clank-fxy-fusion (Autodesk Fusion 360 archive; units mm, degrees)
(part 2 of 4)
sketch "Top Down" plane through (0, 0, 0) normal (0, 0, 1) x axis (1, 0, 0)
  line L1 (13.85, -5.7) -> (56.15, -5.7)
  line L2 (13.85, 36.6) -> (13.85, -5.7)
  line L3 (56.15, 36.6) -> (13.85, 36.6)
  line L4 (56.15, -5.7) -> (56.15, 36.6)
  line L5 (50.5, -0.05) -> (19.5, -0.05)
  line L6 (50.5, 30.95) -> (50.5, -0.05)
  line L7 (19.5, 30.95) -> (50.5, 30.95)
  line L8 (19.5, -0.05) -> (19.5, 30.95)
  line L9 (13.85, 15.45) -> (19.5, 15.45)
  line L10 (35, 36.6) -> (35, 30.95)
  line L11 (35, 15.45) -> (19.5, 15.45)
  line L12 (35, 30.95) -> (35, 15.45)
  line L13 (43.4585, -13.55) -> (45.4793, -10.05)
  line L14 (45.4793, -17.05) -> (43.4585, -13.55)
  line L15 (49.5207, -17.05) -> (45.4793, -17.05)
  line L16 (51.5415, -13.55) -> (49.5207, -17.05)
  line L17 (49.5207, -10.05) -> (51.5415, -13.55)
  line L18 (45.4793, -10.05) -> (49.5207, -10.05)
  line L19 (18.4585, -13.55) -> (20.4793, -10.05)
  line L20 (20.4793, -17.05) -> (18.4585, -13.55)
  line L21 (24.5207, -17.05) -> (20.4793, -17.05)
  line L22 (26.5415, -13.55) -> (24.5207, -17.05)
  line L23 (24.5207, -10.05) -> (26.5415, -13.55)
  line L24 (20.4793, -10.05) -> (24.5207, -10.05)
  line L25 (47.5, -13.55) -> (22.5, -13.55)
  line L26 (100, 14.2247) -> (80, 14.2247)
  line L27 (100, 65.9747) -> (100, 14.2247)
  line L28 (80, 65.9747) -> (100, 65.9747)
  line L29 (80, 14.2247) -> (80, 65.9747)
  line L30 (117, 0) -> (0, 0)
  line L31 (117, -20) -> (117, 0)
  line L32 (0, -20) -> (117, -20)
  line L33 (0, 0) -> (0, -20)
  line L34 (16, 90.9747) -> (16, 40.9747)
  line L35 (113, 90.9747) -> (16, 90.9747)
  line L36 (113, 14.2247) -> (113, 90.9747)
  line L37 (67, 14.2247) -> (113, 14.2247)
  line L38 (117, -21.75) -> (47.5, -21.75)
  line L39 (117, -23.15) -> (117, -21.75)
  line L40 (47.5, -23.15) -> (117, -23.15)
  line L41 (47.5, -21.75) -> (47.5, -23.15)
  line L42 (117, -22) -> (47.5, -22)
  line L43 (30.6969, -13.3244) -> (29.909, 15.3099)
  line L44 (39.3031, -13.3244) -> (40.091, 15.3099)
  line L45 (103.5, 0.15) -> (116.5, 0.15)
  line L46 (103.5, -4.85) -> (103.5, 0.15)
  line L47 (116.5, -4.85) -> (103.5, -4.85)
  line L48 (116.5, 0.15) -> (116.5, -4.85)
  line L49 (67, 40.9747) -> (16, 40.9747)
  line L50 (67, 14.2247) -> (67, 40.9747)
  line L51 (0, 1) -> (117, 1)
  line L52 (0, 13) -> (0, 1)
  line L53 (117, 13) -> (0, 13)
  line L54 (117, 1) -> (117, 13)
  line L55 (63.9793, 3) -> (61.9585, 6.5)
  line L56 (61.9585, 6.5) -> (63.9793, 10)
  line L57 (63.9793, 10) -> (68.0207, 10)
  line L58 (68.0207, 3) -> (63.9793, 3)
  line L59 (68.0207, 10) -> (70.0415, 6.5)
  line L60 (70.0415, 6.5) -> (68.0207, 3)
  line L61 (63.9793, -29.85) -> (61.9585, -26.35)
  line L62 (61.9585, -26.35) -> (63.9793, -22.85)
  line L63 (63.9793, -22.85) -> (68.0207, -22.85)
  line L64 (68.0207, -29.85) -> (63.9793, -29.85)
  line L65 (68.0207, -22.85) -> (70.0415, -26.35)
  line L66 (70.0415, -26.35) -> (68.0207, -29.85)
  line L67 (66, -26.35) -> (66, 6.5)
  line L68 (13.5, -4.85) -> (0.5, -4.85)
  line L69 (13.5, 0.15) -> (13.5, -4.85)
  line L70 (0.5, 0.15) -> (13.5, 0.15)
  line L71 (0.5, -4.85) -> (0.5, 0.15)
  line L72 (0, 37.1) -> (0, 13)
  line L73 (56.65, 37.1) -> (0, 37.1)
  line L74 (56.65, -32.35) -> (56.65, 37.1)
  line L75 (0, -32.35) -> (56.65, -32.35)
  line L76 (0, 1) -> (0, -32.35)
  line L77 (103, -32.35) -> (56.65, -32.35)
  line L78 (103, 1) -> (103, -32.35)
  line L79 (103, 13.4747) -> (103, 1)
  line L80 (56.65, 13.4747) -> (103, 13.4747)
  line L81 (77.5815, -29.81) -> (72.5815, -29.81)
  line L82 (77.5815, -19) -> (77.5815, -29.81)
  line L83 (72.5815, -19) -> (77.5815, -19)
  line L84 (72.5815, -29.81) -> (72.5815, -19)
  line L85 (57.65, -16.46) -> (57.65, -32.35)
  line L86 (77.5815, -16.46) -> (57.65, -16.46)
  line L87 (77.5815, -15.46) -> (77.5815, -16.46)
  line L88 (56.65, -15.46) -> (77.5815, -15.46)
  line L89 (117, -5.7) -> (103, -5.7)
  line L90 (117, -32.35) -> (117, -5.7)
  line L91 (103, -32.35) -> (117, -32.35)
  line L92 (14, -8.85) -> (0, -8.85)
  line L93 (14, 13) -> (14, -8.85)
  line L94 (73, 1) -> (73, 13)
  line L95 (117, -17.5) -> (103, -17.5)
  line L96 (26.0622, 3.5) -> (22.0207, 3.5)
  line L97 (22.0207, 3.5) -> (20, 7)
  line L98 (20, 7) -> (22.0207, 10.5)
  line L99 (22.0207, 10.5) -> (26.0622, 10.5)
  line L100 (28.0829, 7) -> (26.0622, 3.5)
  line L101 (26.0622, 10.5) -> (28.0829, 7)
  line L102 (24.0415, 7) -> (0, 7)
  line L103 (21.3834, 13) -> (21.9245, 6.8148)
  line L104 (19.4009, 13) -> (19.9571, 6.6427)
  line L105 (26.6995, 13) -> (26.1584, 6.8148)
  line L106 (28.682, 13) -> (28.1259, 6.6427)
  line L107 (73, 13.4747) -> (73, 13)
  line L108 (77, -32.35) -> (77, 90.9747)
  line L109 (14, -32.35) -> (14, -8.85)
  line L110 (65.1915, 19.4747) -> (63.1707, 15.9747)
  line L111 (59.1293, 22.9747) -> (63.1707, 22.9747)
  line L112 (57.1085, 19.4747) -> (59.1293, 22.9747)
  line L113 (59.1293, 15.9747) -> (57.1085, 19.4747)
  line L114 (63.1707, 15.9747) -> (59.1293, 15.9747)
  line L115 (63.1707, 22.9747) -> (65.1915, 19.4747)
  line L116 (66.15, 25.4747) -> (66.15, 13.4747)
  line L117 (56.65, 25.4747) -> (66.15, 25.4747)
  line L118 (33.0442, -7.55) -> (32.5754, -14.2545)
  line L119 (35, -13.55) -> (35, 15.45)
  line L120 (36.9558, -7.55) -> (37.4246, -14.2545)
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  point P10 (19.5, 15.45)
  point P12 (35, 30.95)
  point P13 (35, 36.6)
  point P11 (13.85, 15.45)
  point P15 (35, 30.95)
  point P18 (47.5, -13.55)
  point P26 (47.5, -13.55)
  point P19 (22.5, -13.55)
  point P33 (22.5, -13.55)
  point P17 (22.5, -13.55)
  point P34 (22.5, -13.55)
  point P35 (47.5, -13.55)
  point P1 (0, 0)
  point P40 (0, 0)
  point P37 (100, 14.2247)
  point P16 (47.5, -13.55)
  point P54 (47.5, -22)
  point P55 (117, -22)
  point P41 (117, 0)
  point P14 (35, 15.45)
  point P56 (35, 15.45)
  point P61 (16, 65.9747)
  point P49 (67, 14.2247)
  point P67 (67, 14.2247)
  point P46 (113, 90.9747)
  point P47 (113, 90.9747)
  point P75 (66, 6.5)
  point P81 (66, 6.5)
  point P72 (66, 6.5)
  point P85 (66, -26.35)
  point P91 (66, -26.35)
  point P82 (66, -26.35)
  point P92 (66, 6.5)
  point P83 (66, -26.35)
  point P93 (66, -26.35)
  point P64 (103.5, -4.85)
  point P98 (7, -4.85)
  point P69 (0, 1)
  point P103 (0, 1)
  point P105 (103, 1)
  point P107 (56.65, 13.4747)
  point P112 (57.65, -32.35)
  point P116 (56.65, -15.46)
  point P110 (77.5815, -19)
  point P117 (103, -5.7)
  point P104 (103, -32.35)
  point P120 (103, -32.35)
  point P71 (117, 13)
  point P121 (0, -8.85)
  point P123 (14, 13)
  point P124 (73, 13)
  point P125 (73, 1)
  point P126 (103, -17.5)
  point P127 (117, -17.5)
  point P132 (24.0415, 7)
  point P137 (24.0415, 7)
  point P128 (24.0415, 7)
  point P136 (24.0415, 7)
  point P138 (0, 7)
  point P139 (24.0415, 7)
  point P140 (24.0415, 7)
  point P142 (21.3834, 13)
  point P144 (19.4009, 13)
  point P146 (26.6995, 13)
  point P148 (28.682, 13)
  point P150 (73, 13.4747)
  point P151 (110, 0.15)
  point P115 (77.5815, -15.46)
  point P149 (77.5815, -15.46)
  point P152 (77, 90.9747)
  point P153 (77, -32.35)
  point P154 (14, -32.35)
  point P158 (61.15, 19.4747)
  point P164 (61.15, 19.4747)
  point P162 (61.15, 19.4747)
  point P165 (66.15, 13.4747)
  point P167 (56.65, 25.4747)
  point P155 (61.15, 19.4747)
  point P168 (22.5, -13.55)
  point P172 (35, 15.45)
  point P173 (35, -13.55)
  point P174 (47.5, -13.55)
  point P189 (35, -18.55)
  point P191 (35, -18.55)
  point P185 (35, -18.55)
  point P192 (35, -18.55)
  point P182 (35, -18.55)
  point P196 (8.85, -16.2)
  point P202 (8.85, -16.2)
  point P200 (8.85, -16.2)
  point P203 (8.85, -16.2)
  point P207 (8.85, 27.1)
  point P213 (8.85, 27.1)
  point P211 (8.85, 27.1)
  point P214 (8.85, 27.1)
  point P215 (2.85, -8.85)
  point P216 (14, -23.55)
  point P193 (8.85, -16.2)
  point P219 (8.85, -16.2)
  point P221 (8.85, -16.2)
  point P204 (8.85, 27.1)
  point P222 (8.85, 27.1)
  point P223 (2.85, 13)
  point P224 (2.85, 37.1)
  point P226 (61.15, 19.4747)
  point P228 (61.15, 19.4747)
  point P230 (14.1839, -23.55)
  point P231 (14.1839, -23.55)
  point P232 (56.65, -6.3499)
  point P233 (14, 37.1)
  point P240 (61.15, 19.4747)
  point P239 (35, 15.45)
  point P241 (35, 15.45)
  point P242 (61.15, 19.4747)
  point P238 (35.2465, 14.0869)
  point P243 (35.2465, 14.0869)
  point P245 (56.65, -23.55)
  point P246 (0, -23.55)
  point P247 (22.5, -13.55)
  point P251 (22.5, -13.55)
  point P254 (90, 14.2247)
  point P255 (61.15, 19.4747)
  point P257 (61.15, 19.4747)
  point P244 (61.15, 19.4747)
  point P256 (61.15, 19.4747)
  point P3 (13.85, -5.7)
  point P4 (13.85, 36.6)
  point P6 (19.5, -0.05)
  point P9 (19.5, 30.95)
  point P22 (45.4793, -17.05)
  point P36 (80, 14.2247)
  point P43 (0, -20)
  point P44 (16, 40.9747)
  point P45 (16, 90.9747)
  point P50 (47.5, -21.75)
  point P53 (47.5, -23.15)
  point P63 (103.5, 0.15)
  point P62 (116.5, 0.15)
  point P38 (100, 65.9747)
  point P68 (117, 1)
  point P79 (63.9793, 3)
  point P73 (66, 6.5)
  point P89 (63.9793, -29.85)
  point P97 (0.5, 0.15)
  point P108 (72.5815, -29.81)
  point P109 (77.5815, -29.81)
  point P86 (70.0415, -26.35)
  point P122 (14, -8.85)
  point P133 (20, 7)
  point P100 (56.65, 37.1)
  point P94 (0.5, -4.85)
  point P119 (117, -32.35)
  point P101 (56.65, -32.35)
  point P157 (59.1293, 15.9747)
  point P180 (53.5, -7.55)
  point P225 (53.5, -6.55)
  point P106 (103, 13.4747)
  perpendicular L1 L2
  parallel L1 L3
  parallel L2 L4
  perpendicular L5 L6
  parallel L5 L7
  parallel L6 L8
  perpendicular L4 L5
  midpoint L8 P10
  perpendicular L8 L9
  midpoint L7 P12
  perpendicular L7 L10
  midpoint L3 P13
  midpoint L2 P11
  equal L2 L3
  equal L7 L8
  perpendicular L8 L11
  perpendicular L9 L12
  coincident P12 P15
  coincident P18 P26
  coincident P19 P33
  horizontal L24
  horizontal L18
  coincident P17 P34
  horizontal L25
  coincident P26 P35
  horizontal L26
  vertical L27
  horizontal L28
  vertical L29
  horizontal L30
  vertical L31
  horizontal L32
  vertical L33
  coincident P1 P40
  vertical L34
  horizontal L35
  perpendicular L36 L37
  coincident P37 L37
  horizontal L38
  vertical L39
  horizontal L40
  vertical L41
  coincident P16 L41
  coincident L41 P54
  coincident L39 P55
  perpendicular L39 L42
  coincident P41 L39
  coincident P14 P56
  midpoint L34 P61
  coincident L28 P61
  horizontal L45
  vertical L46
  horizontal L47
  vertical L48
  perpendicular L34 L49
  perpendicular L49 L50
  coincident P49 P67
  vertical L36
  coincident P46 P47
  horizontal L51
  vertical L52
  horizontal L53
  vertical L54
  coincident P75 P81
  horizontal L57
  coincident P72 P75
  coincident P85 P91
  horizontal L63
  coincident P82 P85
  coincident P75 P92
  perpendicular L63 L67
  coincident P83 P93
  coincident P41 L54
  horizontal L68
  vertical L69
  horizontal L70
  vertical L71
  equal L46 L71
  equal L47 L70
  coincident P64 L68
  midpoint L68 P98
  perpendicular L53 L72
  perpendicular L72 L73
  perpendicular L40 L74
  perpendicular L74 L75
  perpendicular L32 L76
  coincident P69 P103
  perpendicular L74 L77
  coincident L51 P105
  perpendicular L51 L78
  perpendicular L53 L79
  coincident L74 P107
  perpendicular L74 L80
  horizontal L81
  vertical L82
  horizontal L83
  vertical L84
  coincident L77 P112
  perpendicular L38 L85
  perpendicular L67 L86
  perpendicular L38 L87
  coincident L74 P116
  perpendicular L74 L88
  coincident P110 L87
  coincident L78 P117
  perpendicular L78 L89
  perpendicular L89 L90
  perpendicular L90 L91
  coincident P104 P120
  coincident P71 L90
  coincident L76 P121
  perpendicular L76 L92
  coincident L53 P123
  perpendicular L53 L93
  horizontal L1
  coincident L53 P124
  coincident L51 P125
  perpendicular L51 L94
  coincident L78 P126
  coincident L31 P127
  horizontal L95
  coincident P132 P137
  horizontal L99
  coincident P128 P136
  midpoint L52 P138
  perpendicular L93 L102
  coincident P137 P139
  coincident P128 P137
  coincident P137 P140
  coincident L53 P142
  coincident L53 P144
  parallel L103 L104
  coincident L53 P146
  coincident L53 P148
  parallel L105 L106
  coincident L80 P150
  perpendicular L80 L107
  midpoint L45 P151
  coincident P1 L76
  coincident P115 P149
  coincident L35 P152
  coincident L77 P153
  perpendicular L77 L108
  coincident L75 P154
  perpendicular L75 L109
  coincident P158 P164
  horizontal L111
  coincident P162 P164
  coincident L80 P165
  perpendicular L80 L116
  coincident L74 P167
  perpendicular L74 L117
  coincident P155 P164
  coincident P17 P168
  coincident P56 P172
  midpoint L25 P173
  perpendicular L25 L119
  coincident P18 P174
  coincident P189 P191
  coincident P185 P192
  coincident P182 P185
  coincident P196 P202
  coincident P200 P202
  coincident P196 P203
  coincident P207 P213
  coincident P211 P213
  coincident P207 P214
  coincident L92 P215
  coincident L109 P216
  coincident P193 P196
  coincident P193 P219
  coincident P202 P221
  coincident P204 P222
  coincident P204 P207
  coincident L53 P223
  coincident L73 P224
  coincident P155 P226
  coincident P155 P228
  coincident P230 P231
  coincident L74 P232
  coincident L73 P233
  coincident P158 P240
  coincident P56 P239
  coincident P56 P241
  coincident P155 P242
  coincident P238 P243
  coincident L74 P245
  coincident L76 P246
  coincident P182 P191
  coincident L119 P192
  coincident P17 P247
  coincident P33 P251
  midpoint L37 P254
  coincident P240 P255
  coincident P228 P257
  coincident P240 P244
  coincident P164 P256
  dimension "d583" distance P3 P4 = 42.3
  dimension "d584" distance P6 P9 = 31
  dimension "d588" diameter = 16.4
  dimension "d589" diameter = 4.25 (= "d628")
  dimension "d590" distance P22 L18 = 7 (= "hw_m4hex_d")
  dimension "d591" distance L21 L24 = 7 (= "d590")
  dimension "d592" distance P36 P37 = 20 (= "extrusion_w")
  dimension "d593" distance P40 P43 = 20 (= "extrusion_w")
  dimension "d596" distance P44 P45 = 50
  dimension "d597" distance L29 P49 = 13
  dimension "d598" distance P36 L36 = 33
  dimension "d599" distance P50 P53 = 1.4 (= "t_belt")
  dimension "d600" distance P50 L42 = 0.25 (= "belt_pdo_backside")
  dimension "d607" distance P34 P35 = 25
  dimension "d608" diameter = 10.1859 (= "( 16 * 2 / PI ) * 1 mm")
  dimension "d611" distance L25 P56 = 29
  dimension "d614" distance P63 P64 = 5 (= "t_bearings")
  dimension "d615" distance P62 P63 = 13 (= "od_bearings")
  dimension "d616" distance P38 L34 = 84
  dimension "d617" distance L49 P67 = 26.75
  dimension "d619" distance P68 P71 = 12
  dimension "d620" distance L45 L51 = 0.85 (= "t_m4_washer")
  dimension "d621" distance P41 L51 = 1
  dimension "d622" distance L48 L54 = 0.5
  dimension "d623" diameter = 13 (= "od_bearings")
  dimension "d624" diameter = 4.25 (= "d628")
  dimension "d625" distance P79 L57 = 7 (= "hw_m4hex_d")
  dimension "d626" distance L30 P73 = 6.5 (= "od_bearings / 2")
  dimension "d627" diameter = 13 (= "od_bearings")
  dimension "d628" diameter = 4.25
  dimension "d629" distance P89 L63 = 7 (= "hw_m4hex_d")
  dimension "d630" distance L32 P83 = 6.35 (= "od_bearings / 2 - preload")
  dimension "d631" distance L29 L67 = 14
  dimension "d635" distance L52 P97 = 0.5
  dimension "d636" distance P64 L78 = 0.5
  dimension "d637" distance P85 L77 = 6 (= "od_bearings / 2 - 0.5 mm")
  dimension "d647" distance L77 L81 = 2.54 (= "flex_t")
  dimension "d648" distance P108 P109 = 5 (= "flex_l")
  dimension "d649" distance P86 L84 = 2.54
  dimension "d651" distance L86 L88 = 1
  dimension "d652" distance L83 L86 = 2.54 (= "flex_t")
  dimension "d653" distance L32 L83 = 1
  dimension "d662" distance P64 L89 = 0.85 (= "t_m4_washer")
  dimension "d663" distance L69 P122 = 0.5
  dimension "d669" distance P4 L73 = 0.5
  dimension "d946" distance P73 L94 = 7 (= "od_bearings / 2 + 0.5 mm")
  dimension "d951" distance P71 L95 = 30.5
  dimension "d958" distance L96 L99 = 7 (= "d590")
  dimension "d959" distance L93 P133 = 6
  dimension "d960" diameter = 4.25 (= "d628")
  dimension "d961" diameter = 8.2
  dimension "d962" angle L8 L103 = 5
  dimension "d963" angle L8 L105 = 5
  dimension "d981" distance L4 P100 = 0.5
  dimension "d982" distance L27 P151 = 10
  dimension "d983" distance P94 L92 = 4
  dimension "d990" distance L76 P119 = 117
  dimension "d1027" distance P1 L12 = 35
  dimension "d1028" distance L12 L29 = 45
  dimension "d1029" distance P101 L85 = 1
  dimension "d1031" distance L29 P152 = 3
  dimension "d1033" diameter = 4.25 (= "d628")
  dimension "d1034" distance P157 L111 = 7 (= "hw_m4hex_d")
  dimension "d1035" distance L4 P158 = 5
  dimension "d1036" distance P162 L116 = 5
  dimension "d1037" distance L80 P162 = 6
  dimension "d1038" distance P158 L117 = 6 (= "d1037")
  dimension "d1039" distance = 1.9 (= "t_belt + 0.5 mm")
  dimension "d1042" angle L118 L119 = 4
  dimension "d1043" distance = 1.9 (= "t_belt + 0.5 mm")
  dimension "d1044" angle L119 L120 = 4
  dimension "d1045" distance = 10
  dimension "d1046" distance = 6 (= "od_bearings / 2 - 0.5 mm")
  dimension "d1047" distance = 6
  dimension "d1048" distance = 6
  dimension "d1049" diameter = 4.25 (= "d628")
  dimension "d1050" distance = 7 (= "hw_m4hex_d")
  dimension "d1051" diameter = 4.25 (= "d628")
  dimension "d1052" distance = 7 (= "hw_m4hex_d")
  dimension "d1053" diameter = 4.25 (= "d628")
  dimension "d1054" distance = 7 (= "hw_m4hex_d")
  dimension "d1055" distance = 11
  dimension "d1056" distance L73 P211 = 10
  dimension "d1057" distance P180 P225 = 1
  dimension "d1058" angle = 3
  dimension "d1059" angle = 3 (= "d1058")
  dimension "d1072" distance = 5
  dimension "d1075" radius = 8.5 (= "( 17 / 2 ) * 1 mm")
  dimension "d1076" angle = 3
  dimension "d1430" distance = 77.15
  dimension "d1680" distance L37 P106 = 0.75
  dimension "d1681" distance L32 L42 = 2
  dimension "d1682" distance L25 P191 = 5
  dimension "d1693" distance = 0.5
  dimension "d1697" distance L32 L73 = 57.1
  dimension "d1699" distance = 1.5
  dimension "d1760" distance L53 P165 = 0.4747
  dimension "d523" OffsetX = 0
  dimension "d524" OffsetY = 0
  dimension "d525" OffsetZ = 0
  dimension "d526" AngleZ = 0
  dimension "d567" OffsetX = 0
  dimension "d568" OffsetY = 0
  dimension "d569" OffsetZ = 0
  dimension "d570" AngleZ = 0
extrude "Extrude42" new body sketch "Top Down" along normal blind 9.5 (= "t_sheet_MAIN")
extrude "Extrude44" cut sketch "Top Down" to an object from offset 2
fillet "Fillet17" radius 0.5
fillet "Fillet18" radius 1.5
extrude "Extrude59" new body sketch "Top Down" profile of L51 L52 L53 L54 L79 L93 along normal blind 13.25 (= "od_bearings - 0.5 mm + 0.75 mm")
extrude "Extrude60" new body sketch "Top Down" against normal blind 34.25 (magnitude of "-extrusion_h - 0.75 mm - od_bearings - 0.5 mm")
combine "Combine13"
sketch "Side Plate" plane through (0, 1, 0) normal (0, -1, 0) x axis (1, 0, 0)
  line L1 (14, 0) -> (103, 0)
  line L2 (14, 13.25) -> (14, 0)
  line L3 (0, 13.25) -> (14, 13.25)
  line L4 (0, -34.25) -> (0, 13.25)
  line L5 (117, -34.25) -> (0, -34.25)
  line L6 (117, 13.25) -> (117, -34.25)
  line L7 (103, 13.25) -> (117, 13.25)
  line L8 (103, 0) -> (103, 13.25)
  line L9 (7, 5.75) -> (7, 13.25)
  line L10 (110, 5.75) -> (7, 5.75)
  line L11 (110, -27.1) -> (110, 5.75)
  line L12 (7, -27.1) -> (110, -27.1)
  line L13 (7, 5.75) -> (7, -27.1)
  line L14 (110, 5.75) -> (110, 13.25)
  line L15 (58.5, -34.25) -> (58.5, 0)
  line L16 (7, 9.7915) -> (10.5, 7.7707)
  line L17 (3.5, 7.7707) -> (7, 9.7915)
  line L18 (3.5, 3.7293) -> (3.5, 7.7707)
  line L19 (7, 1.7085) -> (3.5, 3.7293)
  line L20 (10.5, 3.7293) -> (7, 1.7085)
  line L21 (10.5, 7.7707) -> (10.5, 3.7293)
  line L22 (7, -23.0585) -> (10.5, -25.0793)
  line L23 (3.5, -25.0793) -> (7, -23.0585)
  line L24 (3.5, -29.1207) -> (3.5, -25.0793)
  line L25 (7, -31.1415) -> (3.5, -29.1207)
  line L26 (10.5, -29.1207) -> (7, -31.1415)
  line L27 (10.5, -25.0793) -> (10.5, -29.1207)
  line L28 (106.5, 3.7293) -> (110, 1.7085)
  line L29 (106.5, 7.7707) -> (106.5, 3.7293)
  line L30 (110, 9.7915) -> (106.5, 7.7707)
  line L31 (113.5, 7.7707) -> (110, 9.7915)
  line L32 (113.5, 3.7293) -> (113.5, 7.7707)
  line L33 (110, 1.7085) -> (113.5, 3.7293)
  line L34 (18.04, -31.71) -> (13.04, -31.71)
  line L35 (18.04, -24.14) -> (18.04, -31.71)
  line L36 (13.04, -24.14) -> (18.04, -24.14)
  line L37 (13.04, -31.71) -> (13.04, -24.14)
  line L38 (18.04, -21.6) -> (0, -21.6)
  line L39 (18.04, -20.6) -> (18.04, -21.6)
  line L40 (0, -20.6) -> (18.04, -20.6)
  line L41 (103.96, -31.71) -> (103.96, -24.14)
  line L42 (103.96, -24.14) -> (98.96, -24.14)
  line L43 (98.96, -24.14) -> (98.96, -31.71)
  line L44 (98.96, -31.71) -> (103.96, -31.71)
  line L45 (98.96, -20.6) -> (98.96, -21.6)
  line L46 (98.96, -21.6) -> (117, -21.6)
  line L47 (117, -20.6) -> (98.96, -20.6)
  line L48 (110, -23.0585) -> (106.5, -25.0793)
  line L49 (113.5, -25.0793) -> (110, -23.0585)
  line L50 (113.5, -29.1207) -> (113.5, -25.0793)
  line L51 (110, -31.1415) -> (113.5, -29.1207)
  line L52 (106.5, -29.1207) -> (110, -31.1415)
  line L53 (106.5, -25.0793) -> (106.5, -29.1207)
  line L54 (117, 0) -> (103, 0)
  line L55 (80, -20.75) -> (100, -20.75)
  line L56 (80, 39.25) -> (80, -20.75)
  line L57 (100, 39.25) -> (80, 39.25)
  line L58 (100, -20.75) -> (100, 39.25)
  line L59 (90, -20.75) -> (90, 39.25)
  line L60 (76.75, 13.75) -> (78.15, 13.75)
  line L61 (76.75, 24.75) -> (76.75, 13.75)
  line L62 (78.15, 24.75) -> (76.75, 24.75)
  line L63 (78.15, 13.75) -> (78.15, 24.75)
  line L64 (77, 13.75) -> (77, 24.75)
  line L65 (73, 0) -> (103, 0)
  line L66 (73, 9.5) -> (73, 0)
  line L67 (103, 9.5) -> (73, 9.5)
  line L68 (103, 0) -> (103, 9.5)
  line L69 (108.9, 49.75) -> (77, 49.75)
  line L70 (108.9, 9.5) -> (108.9, 49.75)
  line L71 (103, 9.5) -> (108.9, 9.5)
  line L72 (67.9, 12.75) -> (76.9, 12.75)
  line L73 (67.9, 49.75) -> (67.9, 12.75)
  line L74 (76.9, 49.75) -> (67.9, 49.75)
  line L75 (76.9, 12.75) -> (76.9, 49.75)
  line L76 (102.8, 13.45) -> (102.8, 9.5)
  line L77 (108.9, 13.45) -> (102.8, 13.45)
  line L78 (77, 49.75) -> (77, 24.75)
  line L79 (77, 9.5) -> (77, 13.75)
  line L80 (75.75, 24.75) -> (76.75, 24.75)
  line L81 (75.75, 13.75) -> (75.75, 24.75)
  line L82 (76.75, 13.75) -> (75.75, 13.75)
  line L83 (77, 49.75) -> (76.9, 49.75)
  line L84 (57.5, 9.5) -> (73, 9.5)
  line L85 (57.5, 49.75) -> (57.5, 9.5)
  line L86 (67.9, 49.75) -> (57.5, 49.75)
  line L87 (57.5, 12.25) -> (77, 12.25)
  line L88 (0, 0) -> (14, 0)
  line L89 (18.04, -20.6) -> (18.04, 0)
  line L90 (2.85, -20.6) -> (2.85, 0)
  line L91 (39.35, -13.2707) -> (39.35, -9.2293)
  line L92 (46.35, -13.2707) -> (42.85, -15.2915)
  line L93 (46.35, -9.2293) -> (46.35, -13.2707)
  line L94 (42.85, -7.2085) -> (46.35, -9.2293)
  line L95 (42.85, -15.2915) -> (39.35, -13.2707)
  line L96 (39.35, -9.2293) -> (42.85, -7.2085)
  line L97 (39.35, -28.2707) -> (39.35, -24.2293)
  line L98 (42.85, -30.2915) -> (39.35, -28.2707)
  line L99 (46.35, -28.2707) -> (42.85, -30.2915)
  line L100 (42.85, -22.2085) -> (46.35, -24.2293)
  line L101 (46.35, -24.2293) -> (46.35, -28.2707)
  line L102 (39.35, -24.2293) -> (42.85, -22.2085)
  line L103 (42.85, -11.25) -> (42.85, -26.25)
  circle C1 centre (7, 5.75) radius 2.125
  circle C2 centre (7, 5.75) radius 6.5
  circle C3 centre (7, -27.1) radius 2.125
  circle C4 centre (7, -27.1) radius 6.5
  circle C5 centre (110, 5.75) radius 2.125
  circle C6 centre (110, -27.1) radius 2.125
  circle C7 centre (90, 29.25) radius 2.75
  circle C8 centre (90, 9.25) radius 2.75
  circle C9 centre (90, -10.75) radius 2.75
  circle C10 centre (90, 9.25) radius 5.25
  circle C11 centre (90, 29.25) radius 5.25
  circle C12 centre (90, -10.75) radius 5.25
  circle C13 centre (42.85, -11.25) radius 2.125
  circle C14 centre (42.85, -26.25) radius 2.125
  point P12 (7, 13.25)
  point P11 (7, 5.75)
  point P13 (7, 5.75)
  point P10 (7, 5.75)
  point P17 (7, 5.75)
  point P15 (7, -27.1)
  point P20 (7, -27.1)
  point P21 (110, 13.25)
  point P18 (110, 5.75)
  point P22 (110, 5.75)
  point P23 (58.5, 0)
  point P24 (58.5, -34.25)
  point P31 (7, 5.75)
  point P38 (7, -27.1)
  point P25 (10.5, 7.7707)
  point P42 (106.5, 7.7707)
  point P26 (7, 9.7915)
  point P43 (110, 9.7915)
  point P27 (3.5, 7.7707)
  point P44 (113.5, 7.7707)
  point P28 (3.5, 3.7293)
  point P45 (113.5, 3.7293)
  point P29 (7, 1.7085)
  point P40 (110, 1.7085)
  point P30 (10.5, 3.7293)
  point P41 (106.5, 3.7293)
  point P50 (0, -21.6)
  point P53 (0, -20.6)
  point P51 (18.04, -21.6)
  point P32 (10.5, -25.0793)
  point P62 (106.5, -25.0793)
  point P33 (7, -23.0585)
  point P63 (110, -23.0585)
  point P34 (3.5, -25.0793)
  point P64 (113.5, -25.0793)
  point P35 (3.5, -29.1207)
  point P65 (113.5, -29.1207)
  point P36 (7, -31.1415)
  point P66 (110, -31.1415)
  point P37 (10.5, -29.1207)
  point P67 (106.5, -29.1207)
  point P46 (13.04, -31.71)
  point P55 (103.96, -31.71)
  point P47 (18.04, -31.71)
  point P57 (98.96, -31.71)
  point P48 (18.04, -24.14)
  point P56 (98.96, -24.14)
  point P49 (13.04, -24.14)
  point P54 (103.96, -24.14)
  point P60 (117, -21.6)
  point P58 (98.96, -21.6)
  point P52 (18.04, -20.6)
  point P59 (98.96, -20.6)
  point P61 (117, -20.6)
  point P2 (103, 0)
  point P69 (103, 0)
  point P70 (117, 0)
  point P71 (100, 0)
  point P72 (80, 0)
  point P77 (90, 39.25)
  point P78 (90, -20.75)
  point P79 (90, 29.25)
  point P80 (90, 9.25)
  point P81 (90, -10.75)
  point P88 (77, 24.75)
  point P89 (77, 13.75)
  point P90 (78.15, 19.25)
  point P94 (103, 9.5)
  point P98 (103, 9.5)
  point P95 (77, 49.75)
  point P104 (102.8, 9.5)
  point P106 (108.9, 13.45)
  point P108 (77, 9.5)
  point P107 (77, 49.75)
  point P85 (76.75, 13.75)
  point P111 (76.75, 13.75)
  point P93 (73, 9.5)
  point P112 (73, 9.5)
  point P101 (67.9, 49.75)
  point P115 (67.9, 49.75)
  point P116 (77, 12.25)
  point P117 (57.5, 12.25)
  point P3 (14, 0)
  point P119 (14, 0)
  point P14 (0, 0)
  point P120 (0, 0)
  point P121 (18.04, 0)
  point P122 (18.04, -20.6)
  point P123 (2.85, 0)
  point P124 (2.85, -20.6)
  point P125 (42.85, -11.25)
  point P127 (42.85, -11.25)
  point P134 (42.85, -11.25)
  point P126 (42.85, -11.25)
  point P138 (42.85, -26.25)
  point P143 (42.85, -26.25)
  point P139 (42.85, -26.25)
  point P136 (42.85, -26.25)
  point P145 (2.85, 0)
  point P146 (42.85, -26.25)
  point P147 (42.85, -11.25)
  point P16 (7, -27.1)
  point P73 (100, -20.75)
  point P76 (100, 39.25)
  point P86 (76.75, 24.75)
  point P87 (78.15, 24.75)
  point P84 (78.15, 13.75)
  point P75 (80, 39.25)
  point P102 (76.9, 49.75)
  point P96 (108.9, 49.75)
  point P9 (103, 13.25)
  point P109 (75.75, 24.75)
  point P100 (67.9, 12.75)
  point P118 (53.5, 0)
  point P129 (39.35, -9.2293)
  point P141 (39.35, -24.2293)
  concentric C1 C2
  midpoint L3 P12
  perpendicular L3 L9
  coincident P11 P13
  concentric C3 C4
  equal C2 C4
  equal C1 C3
  horizontal L10
  vertical L11
  horizontal L12
  vertical L13
  coincident P10 P17
  coincident P15 P20
  midpoint L7 P21
  perpendicular L7 L14
  coincident P18 P22
  midpoint L1 P23
  perpendicular L5 L15
  coincident L5 P24
  coincident P11 P31
  coincident P15 P38
  vertical L27
  vertical L21
  symmetric C1 L15 C5
  symmetric L15 P25 P42
  symmetric L15 P26 P43
  symmetric L15 P27 P44
  symmetric L15 P28 P45
  symmetric L15 P29 P40
  symmetric L15 P30 P41
  horizontal L34
  vertical L35
  horizontal L36
  vertical L37
  coincident L4 P50
  perpendicular L4 L38
  perpendicular L38 L39
  coincident L4 P53
  perpendicular L4 L40
  coincident L35 P51
  symmetric C3 L15 C6
  symmetric L15 P32 P62
  symmetric L15 P33 P63
  symmetric L15 P34 P64
  symmetric L15 P35 P65
  symmetric L15 P36 P66
  symmetric L15 P37 P67
  symmetric L15 P46 P55
  symmetric L15 P47 P57
  symmetric L15 P48 P56
  symmetric L15 P49 P54
  symmetric L15 P50 P60
  symmetric L15 P51 P58
  symmetric L15 P52 P59
  symmetric L15 P53 P61
  coincident P2 P69
  coincident L6 P70
  perpendicular L6 L54
  horizontal L55
  vertical L56
  horizontal L57
  vertical L58
  coincident P71 L58
  coincident P72 L56
  midpoint L57 P77
  midpoint L55 P78
  coincident L59 P79
  midpoint L59 P80
  coincident L59 P81
  equal C8 C9
  equal C7 C8
  concentric C8 C10
  concentric C7 C11
  equal C10 C11
  horizontal L60
  vertical L61
  horizontal L62
  vertical L63
  coincident L62 P88
  coincident L60 P89
  perpendicular L60 L64
  midpoint L63 P90
  perpendicular L61 L69
  perpendicular L7 L70
  perpendicular L70 L71
  coincident P94 P98
  horizontal L72
  vertical L73
  horizontal L74
  vertical L75
  coincident P95 L74
  concentric C9 C12
  equal C11 C12
  coincident L67 P104
  perpendicular L67 L76
  coincident L70 P106
  perpendicular L70 L77
  perpendicular L62 L78
  coincident L67 P108
  perpendicular L67 L79
  coincident P95 P107
  perpendicular L61 L80
  perpendicular L80 L81
  perpendicular L81 L82
  coincident P85 P111
  coincident P93 P112
  perpendicular L66 L84
  perpendicular L67 L85
  perpendicular L85 L86
  coincident P101 P115
  coincident L79 P116
  coincident L85 P117
  perpendicular L85 L87
  coincident P3 P119
  coincident P14 P120
  coincident L1 P121
  perpendicular L1 L89
  coincident P52 P122
  coincident L88 P123
  coincident L40 P124
  perpendicular L40 L90
  coincident P125 P127
  coincident P125 P134
  vertical L93
  coincident P125 P126
  coincident P138 P143
  coincident P139 P143
  vertical L101
  coincident P136 P143
  coincident L90 P145
  coincident P143 P146
  vertical L103
  coincident P126 P147
  dimension "d928" diameter C2 = 13 (= "od_bearings")
  dimension "d929" distance P10 P14 = 5.75 (= "od_bearings / 2 - 0.75 mm")
  dimension "d930" diameter C1 = 4.25
  dimension "d931" distance P10 P16 = 32.85 (= "extrusion_h + od_bearings - preload")
  dimension "d932" distance P34 L27 = 7 (= "hw_m4hex_d")
  dimension "d933" distance P28 L21 = 7 (= "hw_m4hex_d")
  dimension "d934" distance P51 P52 = 1
  dimension "d935" distance P48 P49 = 5 (= "flex_l")
  dimension "d936" distance L36 P51 = 2.54 (= "flex_t")
  dimension "d937" distance L5 L34 = 2.54 (= "flex_t")
  dimension "d938" distance P32 L37 = 2.54
  dimension "d939" distance P16 L38 = 5.5 (= "od_bearings / 2 - 1 mm")
  dimension "d984" distance P73 P76 = 60
  dimension "d986" distance L10 L55 = 26.5 (= "extrusion_h + od_bearings / 2")
  dimension "d987" diameter C7 = 5.5
  dimension "d988" distance L57 P79 = 10
  dimension "d989" distance L55 P81 = 10
  dimension "d997" diameter C10 = 10.5
  dimension "d1084" distance P86 L64 = 0.25 (= "belt_pdo_backside")
  dimension "d1085" distance P86 P87 = 1.4 (= "t_belt")
  dimension "d1086" distance L56 L64 = 3
  dimension "d1087" distance L57 P90 = 20
  dimension "d1088" distance P84 P87 = 11
  dimension "d1089" distance P75 L69 = 10.5
  dimension "d1091" distance P101 P102 = 9
  dimension "d1092" distance P96 L73 = 41
  dimension "d1093" distance P85 L72 = 1
  dimension "d1100" distance L7 L77 = 0.2
  dimension "d1101" distance P9 L76 = 0.2
  dimension "d1149" distance P95 L75 = 0.1
  dimension "d1150" distance P86 P109 = 1
  dimension "d1151" distance P100 L87 = 0.5
  dimension "d1155" distance L85 P118 = 4
  dimension "d1399" distance P129 L93 = 7 (= "hw_m4hex_d")
  dimension "d1401" distance L90 P126 = 40
  dimension "d1403" diameter C13 = 4.25 (= "hw_m4_thru")
  dimension "d1422" distance P141 L101 = 7 (= "hw_m4hex_d")
  dimension "d1423" diameter C14 = 4.25 (= "hw_m4_thru")
  dimension "d1426" distance L5 P136 = 8
  dimension "d1439" distance P125 P138 = 15
extrude "Extrude61" cut sketch "Side Plate" profile of L4 L6 C1 C3 C5 L34 L35 L36 L37 L38 L39 L40 L41 L42 L43 L44 L45 L46 L47 C6 L55 L58 to an object
extrude "Extrude62" cut sketch "Side Plate" profile of C1 C3 L16 L17 L18 L19 L20 L21 L22 L23 L24 L25 L26 L27 C5 L28 L29 L30 L31 L32 L33 L48 L49 L50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 to an object from offset -2.5
extrude "Extrude136" add of existing geometry blind 2
fillet "Fillet25" radius 0.5
extrude "Extrude63" cut sketch "Top Down" against normal blind 9.85 (magnitude of "-t_bearings - t_m4_washer - 4 mm")
fillet "Fillet30" radius 3
extrude "Extrude65" sketch "Side Plate" profile of L6 L7 L8 C5 L28 L29 L30 L31 L32 L33 L54 to an object
offset_faces "OffsetFaces8" distance -0.125
extrude "Extrude66" cut sketch "Top Down" blind -15 from offset -5.85 (= "-t_bearings - t_m4_washer")
extrude "Extrude67" sketch "Top Down" blind 2
extrude "Extrude68" cut sketch "Top Down" to an object
fillet "Fillet29" radius 2
extrude "Extrude69" cut sketch "Top Down" to an object
extrude "Extrude70" cut sketch "Top Down" to an object from offset 2
offset_faces "OffsetFaces5" distance -0.2
offset_faces "OffsetFaces6" distance -0.2
extrude "Extrude82" sketch "Top Down" blind 6 (= "t_motor_plates") from offset 15.2 (= "13.5 mm + t_m4_washer * 2")
extrude "Extrude83" sketch "Top Down" to an object offset -0.05
combine "Combine15"
sketch "Motor Plate" plane through (0, 0, 30.7) normal (0, 0, 1) x axis (-1, 0, 0)
  line L1 (-56.65, -13.4747) -> (-56.65, 6.3499)
  line L2 (-66.15, -13.4747) -> (-56.65, -13.4747)
  line L3 (-66.15, -25.4747) -> (-66.15, -13.4747)
  line L4 (-56.65, -25.4747) -> (-66.15, -25.4747)
  line L5 (-61.15, -19.4747) -> (-7.0546, 13.4139)
  line L6 (-9.3208, -29.8267) -> (-61.15, -19.4747)
  line L7 (-61.15, -19.4747) -> (-8.85, -27.1)
  line L8 (-61.15, -19.4747) -> (-8.85, 16.2)
  line L9 (-13.85, -36.6) -> (-56.15, -36.6)
  line L10 (-13.85, 5.7) -> (-13.85, -36.6)
  line L11 (-56.15, 5.7) -> (-13.85, 5.7)
  line L12 (-56.15, -36.6) -> (-56.15, 5.7)
  line L13 (-13.85, 5.7) -> (-56.15, -36.6)
  line L14 (-56.15, 5.7) -> (-13.85, -36.6)
  line L15 (-2.85, 21.25) -> (-2.85, -37.1)
  line L16 (-14.3044, 21.25) -> (-2.85, 21.25)
  line L17 (-15.1992, 4.1775) -> (-14.3044, 21.25)
  line L18 (-56.65, 6.3499) -> (-15.1992, 4.1775)
  line L19 (-56.65, -37.1) -> (-56.65, -25.4747)
  line L20 (-2.85, -37.1) -> (-56.65, -37.1)
  circle C1 centre (-35, -15.45) radius 11.05
  circle C2 centre (-50.5, 0.05) radius 1.625
  circle C3 centre (-19.5, 0.05) radius 1.625
  circle C4 centre (-19.5, -30.95) radius 1.625
  circle C5 centre (-50.5, -30.95) radius 1.625
  arc A1 centre (-61.15, -19.4747) radius 65.4336 clockwise from (-7.0945, 17.3974) to (-5.2389, 14.5179)
  arc A2 centre (-7.0546, 13.4139) radius 2.125 clockwise from (-5.2389, 14.5179) to (-8.8704, 12.31)
  arc A3 centre (-61.15, -19.4747) radius 61.1836 clockwise from (-10.6055, 15.0026) to (-8.8704, 12.31)
  arc A4 centre (-8.85, 16.2) radius 2.125 clockwise from (-10.6055, 15.0026) to (-7.0945, 17.3974)
  arc A5 centre (-61.15, -19.4747) radius 63.3086 clockwise from (-8.85, 16.2) to (-7.0546, 13.4139)
  arc A6 centre (-61.15, -19.4747) radius 54.978 clockwise from (-6.7472, -27.4066) to (-7.2369, -30.2429)
  arc A7 centre (-9.3208, -29.8267) radius 2.125 clockwise from (-7.2369, -30.2429) to (-11.4046, -29.4105)
  arc A8 centre (-61.15, -19.4747) radius 50.728 clockwise from (-10.9528, -26.7934) to (-11.4046, -29.4105)
  arc A9 centre (-8.85, -27.1) radius 2.125 clockwise from (-10.9528, -26.7934) to (-6.7472, -27.4066)
  arc A10 centre (-61.15, -19.4747) radius 52.853 clockwise from (-8.85, -27.1) to (-9.3208, -29.8267)
  arc A11 centre (-61.15, -19.4747) radius 68.3086 clockwise from (-4.7194, 19.0175) to (-2.7822, 16.0114)
  arc A12 centre (-7.0546, 13.4139) radius 5 clockwise from (-2.7822, 16.0114) to (-11.327, 10.8165)
  arc A13 centre (-61.15, -19.4747) radius 58.3086 clockwise from (-12.9806, 13.3825) to (-11.327, 10.8165)
  arc A14 centre (-8.85, 16.2) radius 5 clockwise from (-12.9806, 13.3825) to (-4.7194, 19.0175)
  arc A15 centre (-61.15, -19.4747) radius 63.3086 clockwise from (-8.85, 16.2) to (-7.0546, 13.4139)
  arc A16 centre (-61.15, -19.4747) radius 57.853 clockwise from (-3.9023, -27.8214) to (-4.4176, -30.806)
  arc A17 centre (-9.3208, -29.8267) radius 5 clockwise from (-4.4176, -30.806) to (-14.2239, -28.8474)
  arc A18 centre (-61.15, -19.4747) radius 47.853 clockwise from (-13.7977, -26.3786) to (-14.2239, -28.8474)
  arc A19 centre (-8.85, -27.1) radius 5 clockwise from (-13.7977, -26.3786) to (-3.9023, -27.8214)
  arc A20 centre (-61.15, -19.4747) radius 52.853 clockwise from (-8.85, -27.1) to (-9.3208, -29.8267)
  circle C6 centre (-61.15, -19.4747) radius 2.125
  arc A21 centre (-35, -15.45) radius 8.5 clockwise from (-26.5989, -14.157) to (-43.4011, -16.743)
  arc A22 centre (-61.15, -19.4747) radius 17.9579 clockwise from (-43.5684, -15.8178) to (-43.4011, -16.743)
  arc A23 centre (-35.2465, -14.0869) radius 8.5 clockwise from (-43.5684, -15.8178) to (-26.9246, -12.356)
  arc A24 centre (-61.15, -19.4747) radius 34.9579 clockwise from (-26.9246, -12.356) to (-26.5989, -14.157)
  point P7 (-35, -15.45)
  point P14 (-35, -15.45)
  point P8 (-50.5, 0.05)
  point P15 (-50.5, 0.05)
  point P9 (-19.5, 0.05)
  point P16 (-19.5, 0.05)
  point P10 (-19.5, -30.95)
  point P17 (-19.5, -30.95)
  point P11 (-50.5, -30.95)
  point P18 (-50.5, -30.95)
  point P13 (-8.85, 16.2)
  point P23 (-8.85, 16.2)
  point P12 (-8.85, -27.1)
  point P30 (-8.85, -27.1)
  point P24 (-7.0546, 13.4139)
  point P33 (-7.0546, 13.4139)
  point P25 (-61.15, -19.4747)
  point P34 (-61.15, -19.4747)
  point P31 (-9.3208, -29.8267)
  point P35 (-9.3208, -29.8267)
  point P36 (-8.85, -27.1)
  point P32 (-61.15, -19.4747)
  point P37 (-61.15, -19.4747)
  point P38 (-8.85, 16.2)
  point P39 (-61.15, -19.4747)
  point P46 (-61.15, -19.4747)
  point P45 (-7.0546, 13.4139)
  point P52 (-9.3208, -29.8267)
  point P51 (-8.85, -27.1)
  point P44 (-8.85, 16.2)
  point P58 (-35, -15.45)
  point P65 (-61.15, -19.4747)
  point P53 (-61.15, -19.4747)
  point P54 (-56.15, -36.6)
  point P55 (-13.85, -36.6)
  coincident P7 P14
  coincident P8 P15
  coincident P9 P16
  coincident P10 P17
  coincident P11 P18
  equal C3 C4
  equal C2 C4
  equal C4 C5
  tangent A1 A2
  tangent A2 A3
  tangent A3 A4
  tangent A1 A4
  coincident P13 P23
  tangent A6 A7
  tangent A7 A8
  tangent A8 A9
  tangent A6 A9
  coincident P12 P30
  coincident P24 P33
  coincident P25 P34
  coincident P31 P35
  coincident P12 P36
  coincident P32 P37
  coincident P13 P38
  coincident P25 P39
  equal A4 A9
  tangent A11 A12
  tangent A12 A13
  tangent A13 A14
  tangent A11 A14
  coincident P32 P46
  coincident P24 P45
  tangent A16 A17
  tangent A17 A18
  tangent A18 A19
  tangent A16 A19
  coincident P35 P52
  equal A12 A19
  coincident P36 P51
  coincident P38 P44
  horizontal L9
  perpendicular L9 L10
  parallel L9 L11
  parallel L10 L12
  coincident L13 P58
  coincident L14 P58
  coincident P7 P58
  coincident P18 L13
  coincident P25 P65
  coincident P25 P32
  coincident P32 P53
  dimension "d1066" diameter C1 = 22.1
  dimension "d1067" diameter C4 = 3.25
  dimension "d1068" angle L6 L7 = 3
  dimension "d1069" angle L5 L8 = 3 (= "d1068")
  dimension "d1070" radius A4 = 2.125 (= "( 4.25 / 2 ) * 1 mm")
  dimension "d1071" radius A12 = 5
  dimension "d1683" distance P54 P55 = 42.3
extrude "Extrude84" cut sketch "Motor Plate" profile of C1 C2 C3 C4 C5 A1 A2 A3 A4 A6 A7 A8 A9 to an object
extrude "Extrude85" add of existing geometry to an object offset -4
offset_faces "OffsetFaces9" distance -1
chamfer "Chamfer3" distance 9 distance 3
extrude "Extrude86" sketch "Top Down" to an object offset -0.5 from offset 0.05 bodies "Idler Catch"
extrude "Extrude100" cut sketch "Top Down" along normal blind 7
extrude "Extrude101" cut sketch "Top Down" to an object
extrude "Extrude87" sketch "Side Plate" profile of L1 L45 L47 L55 L56 L57 L58 C7 C8 C9 C10 C11 L65 L67 C12 blind 3
extrude "Extrude88" sketch "Side Plate" profile of L56 L57 L58 C7 C8 C10 C11 L67 blind 16
extrude "Extrude89" sketch "Side Plate" profile of L56 L57 L58 L60 L62 L63 L67 L69 L70 L76 L77 to an object
extrude "Extrude90" sketch "Side Plate" profile of L7 L8 L67 L70 L76 L77 to an object
chamfer "Chamfer4" distance 5.85
extrude "Extrude91" sketch "Side Plate" profile of C7 C8 C9 L67 to an object
extrude "Extrude92" sketch "Side Plate" profile of C7 C8 C9 C10 C11 L67 C12 to an object offset -2
extrude "Extrude93" cut sketch "Side Plate" profile of C8 L67 to an object
fillet "Fillet39" radius 2
chamfer "Chamfer5" distance 2.5 (= "( ( 10.5 - 5.5 ) / 2 ) * 1 mm")
offset_faces "OffsetFaces7" distance -0.2
chamfer "Chamfer11" distance 3
chamfer "Chamfer12" distance 0.5
chamfer "Chamfer15" distance 1
chamfer "Chamfer16" distance 1
sketch "Teeth" plane through (0, 0, 13.75) normal (0, 0, 1) x axis (-1, 0, 0)
  line L1 (-78.15, 6) -> (-77, 6)
  line L2 (-78.15, -13) -> (-78.15, 6)
  line L3 (-77, -13) -> (-78.15, -13)
  line L4 (-77.4, -12) -> (-77.4, -12.2607)
  line L5 (-78.15, -12) -> (-77.4, -12)
  line L6 (-77, 6) -> (-77, -13)
  arc A1 centre (-77.6, -13) radius 0.55 clockwise from (-78.15, -13) to (-77.852, -12.5111)
  arc A2 centre (-77.3938, -13.4) radius 1 clockwise from (-77.852, -12.5111) to (-77.5296, -12.4093)
  arc A3 centre (-77.55, -12.2607) radius 0.15 clockwise from (-77.4, -12.2607) to (-77.5296, -12.4093)
  point P4 (-78.15, -13)
  point P6 (-78.15, -13)
  point P9 (-77.5296, -12.4093)
  point P11 (-77.5296, -12.4093)
  point P15 (-78.15, -12)
  point P10 (-77.3938, -13.4)
  point P14 (-77.4, -12)
  tangent L2 A1
  coincident P4 P6
  tangent A1 A2
  coincident P9 P11
  tangent A2 A3
  vertical L4
  coincident L2 P15
  perpendicular L2 L5
  tangent A3 L4
  dimension "d1118" radius A1 = 0.55
  dimension "d1119" radius A2 = 1
  dimension "d1120" distance L3 P10 = 0.4
  dimension "d1121" distance P14 P15 = 0.75
  dimension "d1122" radius A3 = 0.15
  dimension "d1123" distance P6 L5 = 1
extrude "Extrude94" new body sketch "Teeth" profile of L2 A1 A2 A3 L4 L5 to an object
mirror "Mirror5"
combine "Combine16"
rectangular_pattern "R-Pattern1" countU 10 uSpaceDistance -2 vSpaceDistance 0
combine "Combine17"
chamfer "Chamfer7" distance 1.1
extrude "Extrude95" sketch "Side Plate" profile of L72 L73 L74 L75 to an object bodies "Belt Pinch"
sketch "Belt Pinch" plane through (67.9, 0, 0) normal (-1, 0, 0) x axis (0, -1, 0)
  line L1 (6, 49.75) -> (6, 12.75)
  line L2 (-13, 49.75) -> (6, 49.75)
  line L3 (-13, 12.75) -> (-13, 49.75)
  line L4 (6, 12.75) -> (-13, 12.75)
  line L5 (-7, 33.8085) -> (-10.5, 35.8293)
  line L6 (-3.5, 35.8293) -> (-7, 33.8085)
  line L7 (-3.5, 39.8707) -> (-3.5, 35.8293)
  line L8 (-7, 41.8915) -> (-3.5, 39.8707)
  line L9 (-10.5, 39.8707) -> (-7, 41.8915)
  line L10 (-10.5, 35.8293) -> (-10.5, 39.8707)
  line L11 (-2, 33.8707) -> (1.5, 35.8915)
  line L12 (1.5, 35.8915) -> (5, 33.8707)
  line L13 (5, 33.8707) -> (5, 29.8293)
  line L14 (-2, 29.8293) -> (-2, 33.8707)
  line L15 (1.5, 27.8085) -> (-2, 29.8293)
  line L16 (5, 29.8293) -> (1.5, 27.8085)
  line L17 (-13, 25.85) -> (6, 25.85)
  circle C1 centre (-7, 37.85) radius 2.25
  circle C2 centre (1.5, 31.85) radius 2.25
  point P6 (-7, 37.85)
  point P13 (-7, 37.85)
  point P15 (1.5, 31.85)
  point P19 (1.5, 31.85)
  point P22 (-3.5, 49.75)
  point P12 (-10.5, 39.8707)
  point P18 (-2, 33.8707)
  coincident P6 P13
  vertical L10
  coincident P15 P19
  vertical L14
  midpoint L2 P22
  dimension "d1135" distance P12 L7 = 7 (= "hw_m4hex_d")
  dimension "d1136" diameter C1 = 4.5
  dimension "d1137" distance P18 L13 = 7 (= "hw_m4hex_d")
  dimension "d1138" diameter C2 = 4.5
  dimension "d1139" distance P13 P22 = 3.5
  dimension "d1141" distance P15 P22 = 5
  dimension "d1736" distance P6 P15 = 6
  dimension "d1737" distance P19 L17 = 6
extrude "Extrude96" cut sketch "Belt Pinch" profile of C1 C2 to an object
extrude "Extrude97" cut sketch "Belt Pinch" profile of C1 L5 L6 L7 L8 L9 L10 C2 L11 L12 L13 L14 L15 L16 against normal blind 6
chamfer "Chamfer6" distance 2
extrude "Extrude98" sketch "Side Plate" profile of L7 L8 L56 L57 L58 C10 C11 L60 L62 L63 L67 L69 L70 L72 L73 L74 L75 L76 L77 L78 L79 L80 L81 L82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 blind 4
extrude "Extrude99" new body sketch "Side Plate" profile of L67 L79 L84 L85 L87 to an object
combine "Combine18"
extrude "Extrude102" cut sketch "Top Down" to an object
extrude "Extrude108" cut sketch "Side Plate" profile of C13 C14 to an object
extrude "Extrude109" sketch "Side Plate" profile of L91 L92 L93 C13 L94 L95 L96 L97 L98 L99 L100 L101 L102 C14 blind 5.5
chamfer "Chamfer9" distance 2.5
fillet "Fillet56" radius 1
chamfer "Chamfer13" distance 1.6
chamfer "Chamfer14" distance 0.4
sketch "Limit Switch" plane through (0, 13, 0) normal (0, 1, 0) x axis (-1, 0, 0)
  line L1 (-42.85, -7.2085) -> (-46.35, -9.2293)
  line L2 (-39.35, -9.2293) -> (-42.85, -7.2085)
  line L3 (-39.35, -13.2707) -> (-39.35, -9.2293)
  line L4 (-42.85, -15.2915) -> (-39.35, -13.2707)
  line L5 (-46.35, -13.2707) -> (-42.85, -15.2915)
  line L6 (-46.35, -9.2293) -> (-46.35, -13.2707)
  line L7 (-42.85, -22.2085) -> (-46.35, -24.2293)
  line L8 (-39.35, -24.2293) -> (-42.85, -22.2085)
  line L9 (-39.35, -28.2707) -> (-39.35, -24.2293)
  line L10 (-42.85, -30.2915) -> (-39.35, -28.2707)
  line L11 (-46.35, -28.2707) -> (-42.85, -30.2915)
  line L12 (-46.35, -24.2293) -> (-46.35, -28.2707)
  line L13 (-99.1029, -21.45) -> (-79.8, -21.45)
  line L14 (-117, -21.6) -> (-99.46, -21.6)
  line L15 (-117, -34.25) -> (-117, -21.6)
  line L16 (0, -34.25) -> (-117, -34.25)
  line L17 (0, -21.6) -> (0, -34.25)
  line L18 (-17.54, -21.6) -> (0, -21.6)
  line L19 (0, -20.6) -> (-17.54, -20.6)
  line L20 (0, 13.25) -> (0, -20.6)
  line L21 (-14, 13.25) -> (0, 13.25)
  line L22 (-14, 0) -> (-14, 13.25)
  line L23 (-56.65, 0) -> (-14, 0)
  line L24 (-56.65, -6.85) -> (-56.65, 0)
  line L25 (-70, -9.85) -> (-59.65, -9.85)
  line L26 (-73, 0) -> (-73, -6.85)
  line L27 (-79.8, 0) -> (-73, 0)
  line L28 (-106.5, -29.1207) -> (-106.5, -25.0793)
  line L29 (-110, -31.1415) -> (-106.5, -29.1207)
  line L30 (-113.5, -29.1207) -> (-110, -31.1415)
  line L31 (-113.5, -25.0793) -> (-113.5, -29.1207)
  line L32 (-110, -23.0585) -> (-113.5, -25.0793)
  line L33 (-106.5, -25.0793) -> (-110, -23.0585)
  line L34 (-10.5, -29.1207) -> (-7, -31.1415)
  line L35 (-10.5, -25.0793) -> (-10.5, -29.1207)
  line L36 (-7, -23.0585) -> (-10.5, -25.0793)
  line L37 (-3.5, -25.0793) -> (-7, -23.0585)
  line L38 (-3.5, -29.1207) -> (-3.5, -25.0793)
  line L39 (-7, -31.1415) -> (-3.5, -29.1207)
  line L40 (-10.5, 3.7293) -> (-7, 1.7085)
  line L41 (-10.5, 7.7707) -> (-10.5, 3.7293)
  line L42 (-7, 9.7915) -> (-10.5, 7.7707)
  line L43 (-3.5, 7.7707) -> (-7, 9.7915)
  line L44 (-3.5, 3.7293) -> (-3.5, 7.7707)
  line L45 (-7, 1.7085) -> (-3.5, 3.7293)
  line L46 (-103.96, -24.64) -> (-103.96, -31.21)
  line L47 (-99.46, -24.14) -> (-103.46, -24.14)
  line L48 (-98.96, -31.21) -> (-98.96, -24.64)
  line L49 (-103.46, -31.71) -> (-99.46, -31.71)
  line L50 (-13.04, -31.21) -> (-13.04, -24.64)
  line L51 (-17.54, -31.71) -> (-13.54, -31.71)
  line L52 (-18.04, -24.64) -> (-18.04, -31.21)
  line L53 (-13.54, -24.14) -> (-17.54, -24.14)
  line L54 (-26.6995, -3.85) -> (-26.6995, -5.85)
  line L55 (-21.3834, -3.85) -> (-26.6995, -3.85)
  line L56 (-21.3834, -5.85) -> (-21.3834, -3.85)
  line L57 (-19.4009, -5.85) -> (-21.3834, -5.85)
  line L58 (-19.4009, -18.85) -> (-19.4009, -5.85)
  line L59 (-26.6744, -20.85) -> (-21.4085, -20.85)
  line L60 (-28.682, -5.85) -> (-28.682, -18.85)
  line L61 (-26.6995, -5.85) -> (-28.682, -5.85)
  line L62 (-10.2, -0.5) -> (0, -0.5)
  line L63 (-10.2, -20.3) -> (-10.2, -0.5)
  line L64 (0, -20.3) -> (-10.2, -20.3)
  line L65 (0, -0.5) -> (0, -20.3)
  line L66 (-7.7, -15.1) -> (-7.7, -5.6)
  line L67 (-79.8, -21.45) -> (-79.8, 0)
  arc A1 centre (-99.46, -21.1) radius 0.5 clockwise from (-99.1029, -21.45) to (-99.46, -21.6)
  arc A2 centre (-17.54, -21.1) radius 0.5 clockwise from (-17.54, -21.6) to (-17.54, -20.6)
  arc A3 centre (-59.65, -6.85) radius 3 clockwise from (-56.65, -6.85) to (-59.65, -9.85)
  arc A4 centre (-70, -6.85) radius 3 clockwise from (-70, -9.85) to (-73, -6.85)
  arc A5 centre (-103.46, -24.64) radius 0.5 clockwise from (-103.96, -24.64) to (-103.46, -24.14)
  arc A6 centre (-99.46, -24.64) radius 0.5 clockwise from (-99.46, -24.14) to (-98.96, -24.64)
  arc A7 centre (-99.46, -31.21) radius 0.5 clockwise from (-98.96, -31.21) to (-99.46, -31.71)
  arc A8 centre (-103.46, -31.21) radius 0.5 clockwise from (-103.46, -31.71) to (-103.96, -31.21)
  arc A9 centre (-13.54, -31.21) radius 0.5 clockwise from (-13.04, -31.21) to (-13.54, -31.71)
  arc A10 centre (-17.54, -31.21) radius 0.5 clockwise from (-17.54, -31.71) to (-18.04, -31.21)
  arc A11 centre (-17.54, -24.64) radius 0.5 clockwise from (-18.04, -24.64) to (-17.54, -24.14)
  arc A12 centre (-13.54, -24.64) radius 0.5 clockwise from (-13.54, -24.14) to (-13.04, -24.64)
  closed curve K1 centre (-21.4085, -18.85)
  closed curve K2 centre (-26.6744, -18.85)
  circle C1 centre (-7.7, -15.1) radius 0.9
  circle C2 centre (-7.7, -5.6) radius 0.9
  point P97 (-7.7, -15.1)
  point P98 (-7.7, -15.1)
  point P96 (-7.7, -5.6)
  point P99 (-7.7, -5.6)
  point P100 (-7.7, -5.6)
  point P101 (-7.7, -15.1)
  point P25 (0, -20.6)
  point P93 (-10.2, -0.5)
  point P94 (-10.2, -20.3)
  point P92 (0, -0.5)
  point P1 (0, 0)
  horizontal L62
  vertical L63
  horizontal L64
  vertical L65
  vertical L66
  coincident P97 P98
  coincident P96 P99
  equal C1 C2
  coincident P96 P100
  coincident P98 P101
  coincident P25 L65
  dimension "d1738" distance P93 P94 = 19.8
  dimension "d1739" diameter C2 = 1.8
  dimension "d1742" distance P96 P97 = 9.5
  dimension "d1743" distance L62 P99 = 5.1
  dimension "d1744" distance P92 P93 = 10.2
  dimension "d1745" distance P1 L62 = 0.5
  dimension "d1746" distance L63 L66 = 2.5
extrude "Extrude118" cut sketch "Limit Switch" profile of C1 C2 to an object
chamfer "Chamfer20" distance 0.6 distance 1
extrude "Extrude120" cut of existing geometry to an object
